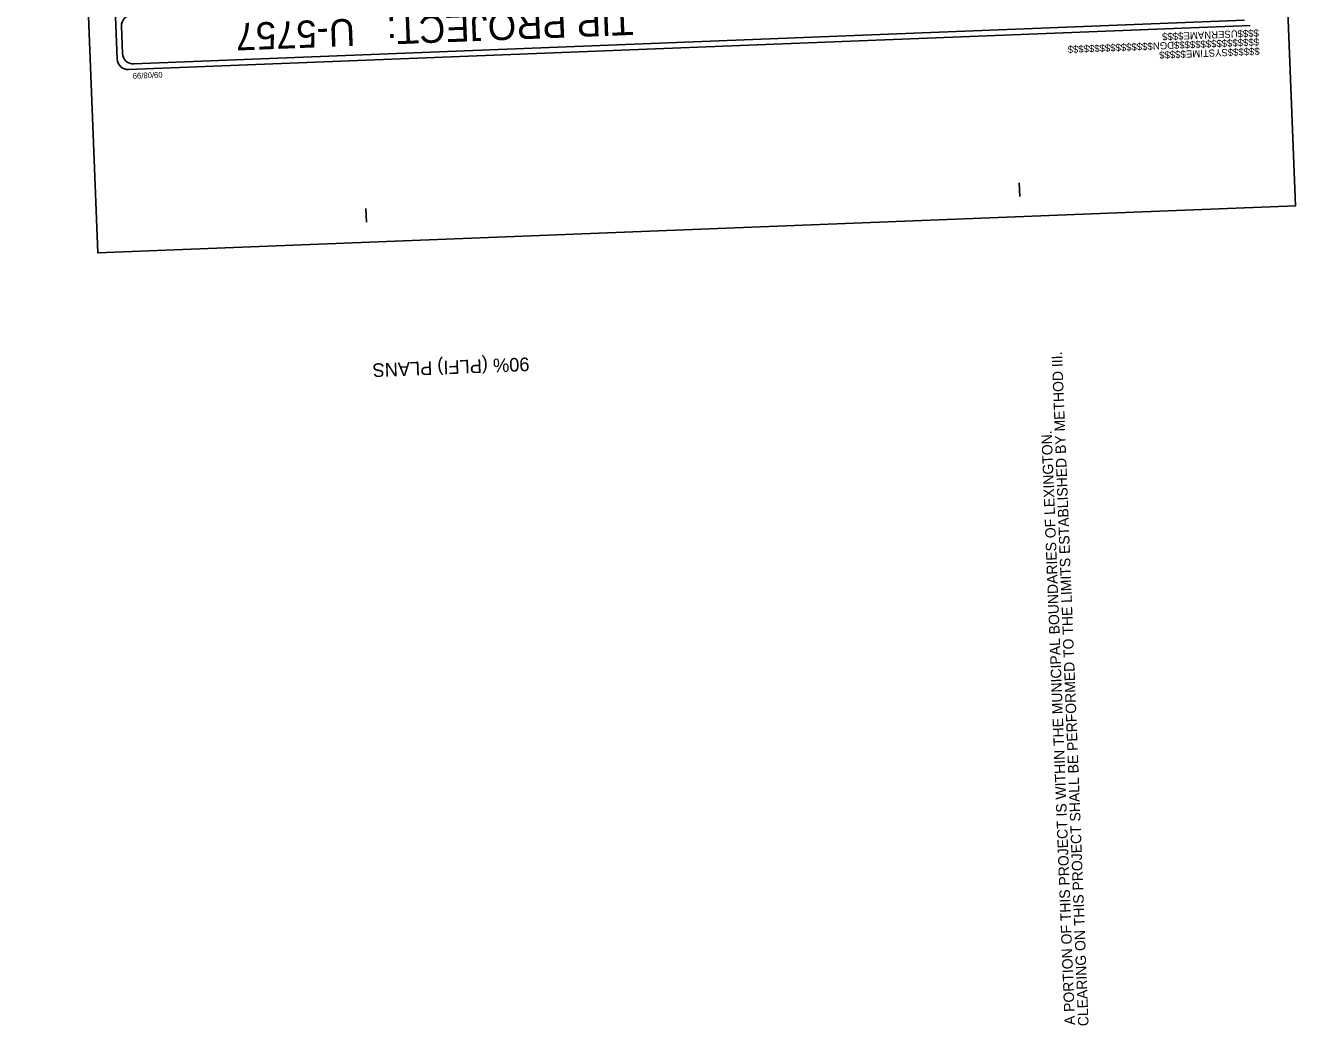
# Model space of a CAD drawing. Extents: x 1624323 to 1631382, y 753034 to 769560.
# Drawn here: x 1624323 to 1631382, y 753034 to 758593 of the extents above; entities that cross this region are included whole.
import ezdxf

# ---------------------------------------------------------------- set-up
doc = ezdxf.new("R2010")
doc.units = 0
for name, color, linetype in [('Old_Level_1', 7, 'Continuous'), ('Sheet Plot Border Outside CELL', 7, 'Continuous'), ('Sheet Title CELL', 7, 'Continuous')]:
    doc.layers.add(name, color=color, linetype=linetype)

msp = doc.modelspace()

# ---------------------------------------------------------------- linework, layer by layer
at = {"layer": 'Sheet Plot Border Outside CELL'}
msp.add_lwpolyline([(1624322.9, 767519.9), (1624724.8, 757327.8), (1631382.3, 757590.3), (1630980.3, 767782.4)], close=True, dxfattribs=at)
at = {"layer": 'Sheet Title CELL'}
for p, q in [((1629849.7, 757642.1), (1629846.6, 757717.7)), ((1629849.7, 757642.1), (1629846.6, 757717.7)), ((1626218.3, 757498.9), (1626215.3, 757574.5)), ((1626218.3, 757498.9), (1626215.3, 757574.5))]:
    msp.add_line(p, q, dxfattribs=at)
for points in [[(1624480.6, 767362.5), (1624833.8, 758405)], [(1624925.8, 758378.4), (1631099.1, 758621.8)], [(1624857, 758587.8), (1624862.9, 758436.5)], [(1624896.7, 758346.9), (1631130.6, 758592.7)], [(1624896.7, 758346.9), (1631130.6, 758592.7)]]:
    msp.add_lwpolyline(points, dxfattribs=at)
for centre, start, end in [((1624917.1, 758590.2), 92.25819, 182.25819), ((1624894, 758407.4), 182.25819, 272.25819), ((1624923.1, 758438.9), 182.25819, 272.25819)]:
    msp.add_arc(centre, 60.6, start, end, dxfattribs=at)

# ---------------------------------------------------------------- texts
at = {"layer": 'Old_Level_1'}
for s, p in [('CLEARING ON THIS PROJECT SHALL BE PERFORMED TO THE LIMITS ESTABLISHED BY METHOD III.', (1630232, 753031.3)), ('A PORTION OF THIS PROJECT IS WITHIN THE MUNICIPAL BOUNDARIES OF LEXINGTON.', (1630156.8, 753037.5))]:
    msp.add_text(s, height=58.046, rotation=92.25819, dxfattribs=at).set_placement(p)
at = {"layer": 'Sheet Title CELL'}
for s, height, p in [('TIP PROJECT:', 151.425, (1627698.9, 758691.5)), ('U-5757', 151.43, (1626152.1, 758630.5)), ('$$$$USERNAME$$$$', 39.749, (1631177.9, 758570.3)), ('$$$$$$$$$$$$$$$$DGN$$$$$$$$$$$$$$$$', 39.749, (1631178.8, 758520.6)), ('$$$$$$SYSTIME$$$$$', 39.749, (1631182.3, 758469.2)), ('09/08/99', 31.8, (1625084.3, 758334.6)), ('90% (PLFI) PLANS', 75.713, (1627122.6, 756747.7))]:
    msp.add_text(s, height=height, rotation=182.25819, dxfattribs=at).set_placement(p)

doc.saveas('drawing.dxf')
